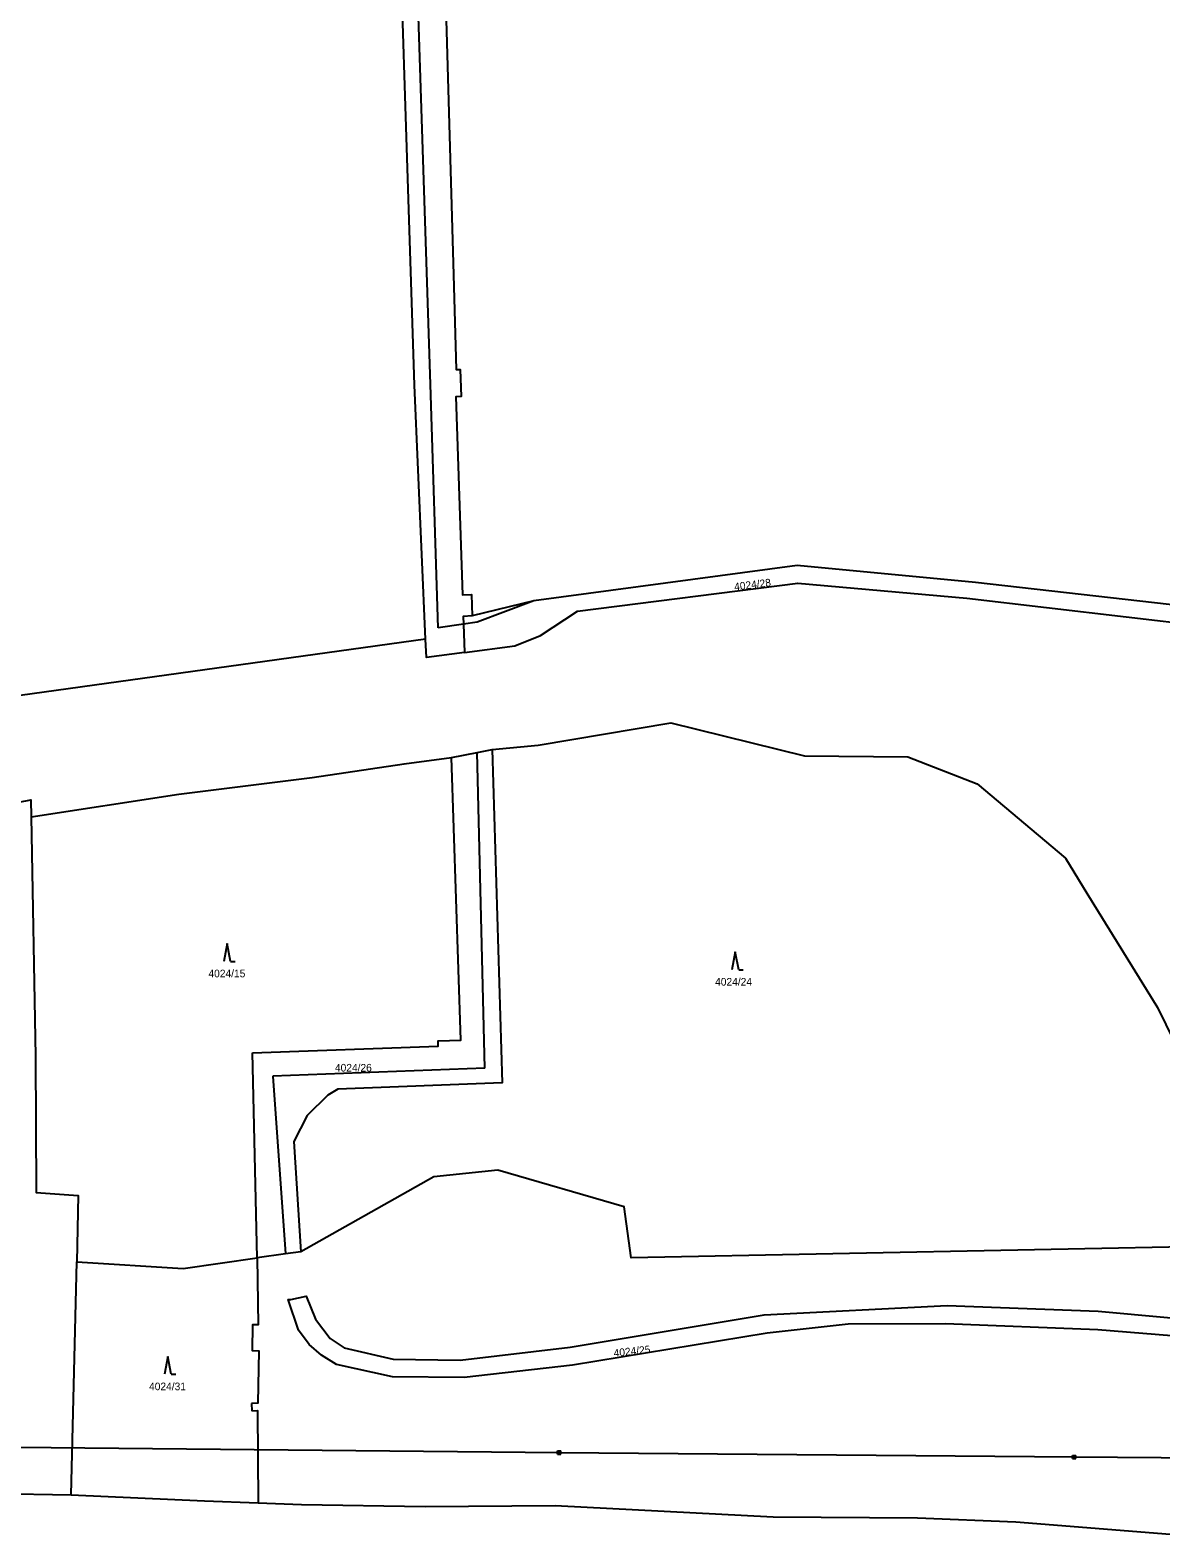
# Model space of a CAD drawing. Extents: x -869103 to -863415, y -1015889 to -1012477.
# Drawn here: x -868460.7 to -868208.8, y -1015850.5 to -1015514.6 of the extents above; entities that cross this region are included whole.
import ezdxf

# ---------------------------------------------------------------- set-up
doc = ezdxf.new("R2010")
doc.units = 0
for name, color, linetype in [('Hranice katastralního území', 7, 'Continuous'), ('Hranice parcel', 7, 'Continuous'), ('Parcelní čísla', 7, 'Continuous'), ('Poz předměty', 7, 'Continuous'), ('Vnitřní kresba', 7, 'Continuous'), ('Značky kultur', 7, 'Continuous')]:
    doc.layers.add(name, color=color, linetype=linetype)

msp = doc.modelspace()

# ---------------------------------------------------------------- linework, layer by layer
at = {"layer": 'Hranice katastralního území'}
for p, q in [((-868507.01, -1015839.98), (-868451.6, -1015840.94)), ((-868451.6, -1015840.94), (-868421.88, -1015842.24)), ((-868421.88, -1015842.24), (-868409.9, -1015842.72)), ((-868409.9, -1015842.72), (-868400.29, -1015843.11)), ((-868400.29, -1015843.11), (-868372.7, -1015843.49)), ((-868263.05, -1015846.04), (-868241.11, -1015846.95)), ((-868241.11, -1015846.95), (-868196.12, -1015850.51))]:
    msp.add_line(p, q, dxfattribs=at)
msp.add_lwpolyline([(-868372.7, -1015843.49), (-868343.75, -1015843.28), (-868295.17, -1015845.84), (-868263.05, -1015846.04)], dxfattribs=at)
at = {"layer": 'Hranice parcel'}
for p, q in [((-868460.52, -1015689.88), (-868427.6, -1015684.81)), ((-868410.14, -1015788.15), (-868411.15, -1015742.44)), ((-868451.6, -1015840.94), (-868450.36, -1015789.02)), ((-868450.36, -1015789.02), (-868426.66, -1015790.51)), ((-868426.66, -1015790.51), (-868410.14, -1015788.15)), ((-868411.42, -1015820.58), (-868411.32, -1015822.21)), ((-868507.01, -1015839.98), (-868451.6, -1015840.94)), ((-868451.6, -1015840.94), (-868421.88, -1015842.24)), ((-868421.88, -1015842.24), (-868409.9, -1015842.72)), ((-868409.9, -1015842.72), (-868400.29, -1015843.11)), ((-868400.29, -1015843.11), (-868372.7, -1015843.49)), ((-868263.05, -1015846.04), (-868241.11, -1015846.95)), ((-868241.11, -1015846.95), (-868196.12, -1015850.51))]:
    msp.add_line(p, q, dxfattribs=at)
for points in [[(-868372.62, -1015650.31), (-868375.06, -1015593.7), (-868379.77, -1015448.5), (-868381.29, -1015399.04), (-868385.49, -1015267.14), (-868385.14, -1015257.18), (-868382.42, -1015249.86), (-868337.64, -1015162.28), (-868270.87, -1015031.23), (-868224.71, -1014936.44), (-868217.46, -1014921.88), (-868187.29, -1014860.17), (-868124.41, -1014730.67), (-868094.56, -1014686.21), (-868057.83, -1014631.35), (-868034.61, -1014596.71), (-868032.42, -1014593.94), (-867916.32, -1014490.06), (-867912.24, -1014486.43), (-867903.51, -1014483.24), (-867819.68, -1014475.16), (-867775.62, -1014471.67)], [(-868370.23, -1015437.27), (-868366.4, -1015569.11), (-868365.79, -1015590.23), (-868364.92, -1015590.21), (-868364.7, -1015596.24), (-868365.91, -1015596.3), (-868364.41, -1015640.41), (-868362.41, -1015640.32), (-868362.24, -1015645.12)], [(-868173.11, -1015647.71), (-868175.83, -1015643.51), (-868192.94, -1015643.03), (-868193.23, -1015644.14), (-868250.08, -1015637.69), (-868289.83, -1015633.9), (-868348.51, -1015641.71), (-868362.24, -1015645.12)], [(-868363.98, -1015653.24), (-868352.74, -1015651.74), (-868347.03, -1015649.48), (-868338.79, -1015644.08), (-868289.71, -1015637.83), (-868252.02, -1015641.15), (-868181.03, -1015649.49), (-868178.11, -1015654.39), (-868172.1, -1015654.07), (-868173.11, -1015647.71)], [(-868362.24, -1015645.12), (-868364.25, -1015645.2), (-868364.19, -1015646.94), (-868363.98, -1015653.24)], [(-868372.62, -1015650.31), (-868569.92, -1015677.67)], [(-868363.98, -1015653.24), (-868372.44, -1015654.37), (-868372.62, -1015650.31)], [(-868357.77, -1015674.86), (-868347.51, -1015673.88), (-868318.01, -1015668.89)], [(-868318.01, -1015668.89), (-868288.2, -1015676.28), (-868265.16, -1015676.48)], [(-868357.77, -1015674.86), (-868355.58, -1015749.12), (-868392.21, -1015750.57), (-868394.37, -1015751.86), (-868399.01, -1015756.44), (-868402, -1015762.21), (-868400.45, -1015786.77)], [(-868366.85, -1015676.67), (-868361.15, -1015675.53), (-868357.77, -1015674.86)], [(-868427.6, -1015684.81), (-868397.91, -1015681.13), (-868377.42, -1015678.04), (-868366.85, -1015676.67)], [(-868411.15, -1015742.44), (-868369.81, -1015740.94), (-868369.84, -1015739.81), (-868364.77, -1015739.59), (-868366.85, -1015676.67)], [(-868265.16, -1015676.48), (-868249.76, -1015682.53), (-868230.07, -1015699.07), (-868225.27, -1015706.86), (-868209.56, -1015732.38), (-868196.38, -1015759.16), (-868191.18, -1015773.23), (-868192, -1015785.48), (-868326.85, -1015788.15), (-868328.35, -1015776.75), (-868356.53, -1015768.6), (-868370.79, -1015770.11), (-868400.45, -1015786.77)], [(-868664.22, -1015721.96), (-868656.68, -1015698.42), (-868636.88, -1015700.24), (-868609.97, -1015703.63), (-868592.54, -1015702.6), (-868568.45, -1015700.22), (-868533.04, -1015695.09), (-868507.46, -1015693.19), (-868474.41, -1015688.75), (-868460.59, -1015686.1), (-868460.52, -1015689.88)], [(-868460.52, -1015689.88), (-868459.5, -1015743.2), (-868459.36, -1015773.53), (-868450, -1015774.2), (-868450.36, -1015789.02)], [(-868400.45, -1015786.77), (-868403.83, -1015787.25), (-868410.14, -1015788.15)], [(-868410.14, -1015788.15), (-868409.93, -1015803.03), (-868411.17, -1015803.03), (-868411.23, -1015808.79), (-868409.81, -1015808.86), (-868410.02, -1015820.54), (-868411.42, -1015820.58)], [(-868192.8, -1015806.59), (-868222.85, -1015804.19), (-868256.82, -1015802.85), (-868278.51, -1015802.93), (-868296.52, -1015804.9), (-868339.93, -1015812.07), (-868364.05, -1015814.82), (-868379.99, -1015814.64), (-868392.45, -1015811.88), (-868395.83, -1015809.83), (-868398.59, -1015807.46), (-868400.93, -1015804.23), (-868403.23, -1015797.44), (-868402.63, -1015797.44), (-868399.2, -1015796.67), (-868397.18, -1015801.82), (-868393.88, -1015806.09), (-868390.77, -1015808.17), (-868379.83, -1015810.67), (-868364.94, -1015810.9), (-868340.38, -1015808), (-868297.16, -1015800.84), (-868256.45, -1015798.72), (-868222.77, -1015800), (-868191.89, -1015802.8)], [(-868411.32, -1015822.21), (-868410.11, -1015822.14), (-868409.9, -1015842.72)], [(-868372.7, -1015843.49), (-868343.75, -1015843.28), (-868295.17, -1015845.84), (-868263.05, -1015846.04)]]:
    msp.add_lwpolyline(points, dxfattribs=at)
at = {"layer": 'Poz předměty'}
for p, q in [((-868343.22, -1015831.16), (-868342.52, -1015831.16)), ((-868343.22, -1015831.86), (-868343.22, -1015831.16)), ((-868343.22, -1015831.3), (-868342.52, -1015831.3)), ((-868343.22, -1015831.44), (-868342.52, -1015831.44)), ((-868343.22, -1015831.58), (-868342.52, -1015831.58)), ((-868343.22, -1015831.72), (-868342.52, -1015831.72)), ((-868343.22, -1015831.86), (-868342.52, -1015831.86)), ((-868343.08, -1015831.86), (-868343.08, -1015831.16)), ((-868342.94, -1015831.86), (-868342.94, -1015831.16)), ((-868342.8, -1015831.86), (-868342.8, -1015831.16)), ((-868342.66, -1015831.86), (-868342.66, -1015831.16)), ((-868342.52, -1015831.86), (-868342.52, -1015831.16)), ((-868228.48, -1015832.14), (-868227.78, -1015832.14)), ((-868228.48, -1015832.84), (-868228.48, -1015832.14)), ((-868228.48, -1015832.28), (-868227.78, -1015832.28)), ((-868228.48, -1015832.42), (-868227.78, -1015832.42)), ((-868228.48, -1015832.56), (-868227.78, -1015832.56)), ((-868228.48, -1015832.7), (-868227.78, -1015832.7)), ((-868228.48, -1015832.84), (-868227.78, -1015832.84)), ((-868228.34, -1015832.84), (-868228.34, -1015832.14)), ((-868228.2, -1015832.84), (-868228.2, -1015832.14)), ((-868228.06, -1015832.84), (-868228.06, -1015832.14)), ((-868227.92, -1015832.84), (-868227.92, -1015832.14)), ((-868227.78, -1015832.84), (-868227.78, -1015832.14))]:
    msp.add_line(p, q, dxfattribs=at)
for points in [[(-868228.13, -1015832.49), (-868131.39, -1015833.22), (-867926.44, -1015699.01)], [(-868486.35, -1015830.09), (-868342.87, -1015831.51), (-868228.13, -1015832.49)]]:
    msp.add_lwpolyline(points, dxfattribs=at)
at = {"layer": 'Vnitřní kresba'}
for p, q in [((-868371.54, -1015593.57), (-868376.25, -1015448.1)), ((-868369.79, -1015647.76), (-868371.54, -1015593.57)), ((-868348.51, -1015641.71), (-868361.13, -1015646.49)), ((-868364.19, -1015646.94), (-868369.79, -1015647.76)), ((-868361.13, -1015646.49), (-868364.19, -1015646.94)), ((-868359.43, -1015745.87), (-868361.15, -1015675.53)), ((-868359.43, -1015745.87), (-868406.66, -1015747.62)), ((-868406.66, -1015747.62), (-868403.83, -1015787.25))]:
    msp.add_line(p, q, dxfattribs=at)
at = {"layer": 'Značky kultur'}
for p, q in [((-868416.83, -1015718.07), (-868417.58, -1015722.07)), ((-868416.08, -1015722.07), (-868416.83, -1015718.07)), ((-868416.08, -1015722.07), (-868415.08, -1015722.07)), ((-868303.62, -1015719.92), (-868304.37, -1015723.92)), ((-868302.87, -1015723.92), (-868303.62, -1015719.92)), ((-868302.87, -1015723.92), (-868301.87, -1015723.92)), ((-868430.03, -1015810.07), (-868430.78, -1015814.07)), ((-868429.28, -1015814.07), (-868430.03, -1015810.07)), ((-868429.28, -1015814.07), (-868428.28, -1015814.07))]:
    msp.add_line(p, q, dxfattribs=at)

# ---------------------------------------------------------------- texts
at = {"layer": 'Parcelní čísla'}
for s, rotation, p in [('4024/28', 7, (-868303.76, -1015639.47)), ('4024/25', 6, (-868330.63, -1015810.19))]:
    msp.add_text(s, height=1.7, rotation=rotation, dxfattribs=at).set_placement(p)
for s, p in [('4024/15', (-868421, -1015725.62)), ('4024/24', (-868308.12, -1015727.47)), ('4024/26', (-868392.82, -1015746.62)), ('4024/31', (-868434.23, -1015817.62))]:
    msp.add_text(s, height=1.7, dxfattribs=at).set_placement(p)

doc.saveas('drawing.dxf')
